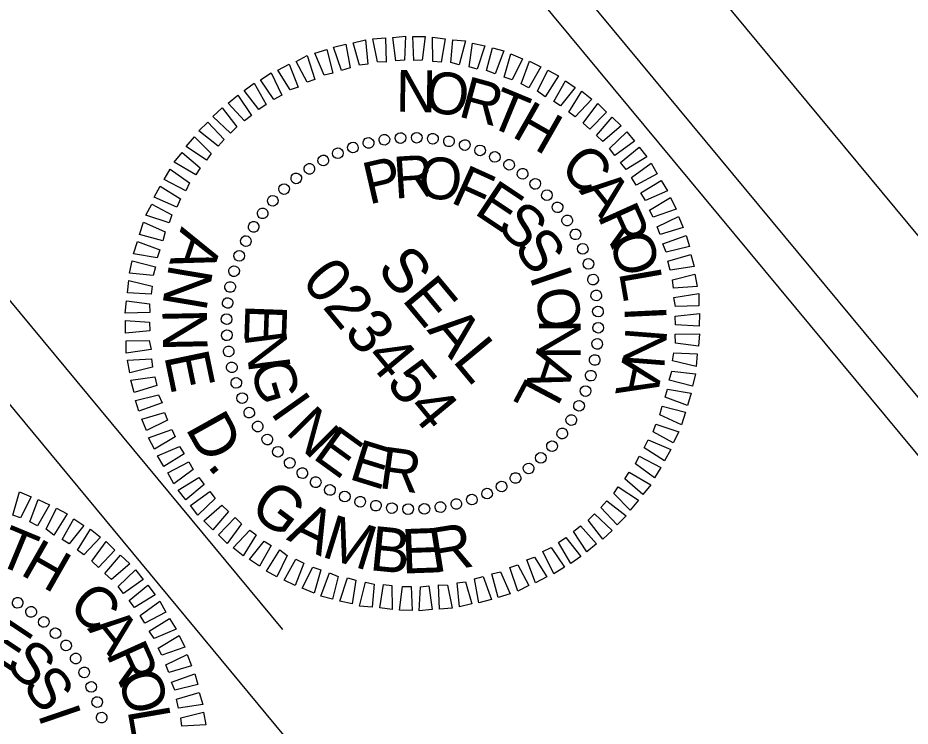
# Model space of a CAD drawing. Extents: x 2054826 to 2060231, y 685508 to 690809.
# Drawn here: x 2058800.7 to 2058981.3, y 687724.9 to 687868.3 of the extents above; entities that cross this region are included whole.
import ezdxf

# ---------------------------------------------------------------- set-up
doc = ezdxf.new("R2010")
doc.units = 0
for name, color, linetype in [('Old_Level_21', 7, 'Continuous'), ('Sheet Professional Seal CELL', 7, 'Continuous'), ('Sheet Title CELL', 7, 'Continuous')]:
    doc.layers.add(name, color=color, linetype=linetype)

msp = doc.modelspace()

# ---------------------------------------------------------------- linework, layer by layer
at = {"layer": 'Old_Level_21'}
msp.add_lwpolyline([(2058588.27, 689338), (2059498.4, 688240.46), (2058988.43, 687817.56), (2058078.29, 688915.11)], close=True, dxfattribs=at)
at = {"layer": 'Sheet Professional Seal CELL'}
for p, q in [((2058874.87, 687843.74), (2058874.87, 687843.74)), ((2058878.15, 687844.02), (2058878.15, 687844.02)), ((2058881.46, 687844.13), (2058881.46, 687844.13)), ((2058884.69, 687843.89), (2058884.69, 687843.89)), ((2058888, 687843.42), (2058888, 687843.42)), ((2058868.49, 687842.15), (2058868.49, 687842.15)), ((2058871.66, 687843.02), (2058871.66, 687843.02)), ((2058891.12, 687842.59), (2058891.12, 687842.59)), ((2058894.26, 687841.5), (2058894.26, 687841.5)), ((2058865.4, 687840.95), (2058865.4, 687840.95)), ((2058897.29, 687840.21), (2058897.29, 687840.21)), ((2058862.54, 687839.46), (2058862.54, 687839.46)), ((2058900.12, 687838.66), (2058900.12, 687838.66)), ((2058859.72, 687837.8), (2058859.72, 687837.8)), ((2058902.83, 687836.81), (2058902.83, 687836.81)), ((2058857.04, 687835.87), (2058857.04, 687835.87)), ((2058905.4, 687834.66), (2058905.4, 687834.66)), ((2058854.55, 687833.7), (2058854.55, 687833.7)), ((2058907.8, 687832.46), (2058907.8, 687832.46)), ((2058852.35, 687831.3), (2058852.35, 687831.3)), ((2058909.96, 687829.97), (2058909.96, 687829.97)), ((2058850.19, 687828.73), (2058850.19, 687828.73)), ((2058911.9, 687827.28), (2058911.9, 687827.28)), ((2058848.34, 687826.03), (2058848.34, 687826.03)), ((2058913.55, 687824.47), (2058913.55, 687824.47)), ((2058846.8, 687823.19), (2058846.8, 687823.19)), ((2058915.04, 687821.61), (2058915.04, 687821.61)), ((2058845.51, 687820.17), (2058845.51, 687820.17)), ((2058916.25, 687818.52), (2058916.25, 687818.52)), ((2058844.41, 687817.02), (2058844.41, 687817.02)), ((2058917.12, 687815.35), (2058917.12, 687815.35)), ((2058843.59, 687813.9), (2058843.59, 687813.9)), ((2058917.83, 687812.14), (2058917.83, 687812.14)), ((2058843.12, 687810.59), (2058843.12, 687810.59)), ((2058842.87, 687807.36), (2058842.87, 687807.36)), ((2058918.11, 687808.86), (2058918.11, 687808.86)), ((2058880.55, 687806.46), (2058880.55, 687806.46)), ((2058918.23, 687805.55), (2058918.23, 687805.55)), ((2058842.99, 687804.05), (2058842.99, 687804.05)), ((2058917.98, 687802.32), (2058917.98, 687802.32)), ((2058843.27, 687800.77), (2058843.27, 687800.77)), ((2058917.51, 687799.01), (2058917.51, 687799.01)), ((2058843.98, 687797.56), (2058843.98, 687797.56)), ((2058916.69, 687795.89), (2058916.69, 687795.89)), ((2058844.86, 687794.39), (2058844.86, 687794.39)), ((2058915.6, 687792.74), (2058915.6, 687792.74)), ((2058846.06, 687791.3), (2058846.06, 687791.3)), ((2058914.3, 687789.72), (2058914.3, 687789.72)), ((2058847.55, 687788.44), (2058847.55, 687788.44)), ((2058849.21, 687785.63), (2058849.21, 687785.63)), ((2058912.76, 687786.88), (2058912.76, 687786.88)), ((2058910.91, 687784.18), (2058910.91, 687784.18)), ((2058851.14, 687782.94), (2058851.14, 687782.94)), ((2058853.3, 687780.45), (2058853.3, 687780.45)), ((2058908.75, 687781.61), (2058908.75, 687781.61)), ((2058855.71, 687778.25), (2058855.71, 687778.25)), ((2058906.56, 687779.21), (2058906.56, 687779.21)), ((2058904.07, 687777.04), (2058904.07, 687777.04)), ((2058858.28, 687776.1), (2058858.28, 687776.1)), ((2058901.38, 687775.11), (2058901.38, 687775.11)), ((2058860.98, 687774.25), (2058860.98, 687774.25)), ((2058898.56, 687773.45), (2058898.56, 687773.45)), ((2058863.82, 687772.7), (2058863.82, 687772.7)), ((2058866.84, 687771.41), (2058866.84, 687771.41)), ((2058895.71, 687771.96), (2058895.71, 687771.96)), ((2058869.99, 687770.32), (2058869.99, 687770.32)), ((2058873.11, 687769.49), (2058873.11, 687769.49)), ((2058889.44, 687769.89), (2058889.44, 687769.89)), ((2058892.61, 687770.76), (2058892.61, 687770.76)), ((2058876.42, 687769.02), (2058876.42, 687769.02)), ((2058879.65, 687768.78), (2058879.65, 687768.78)), ((2058882.96, 687768.89), (2058882.96, 687768.89)), ((2058886.23, 687769.17), (2058886.23, 687769.17)), ((2058803.37, 687748.12), (2058803.37, 687748.12)), ((2058805.94, 687745.96), (2058805.94, 687745.96)), ((2058808.35, 687743.76), (2058808.35, 687743.76)), ((2058810.51, 687741.27), (2058810.51, 687741.27)), ((2058812.44, 687738.59), (2058812.44, 687738.59)), ((2058814.1, 687735.77), (2058814.1, 687735.77)), ((2058815.59, 687732.91), (2058815.59, 687732.91)), ((2058816.79, 687729.82), (2058816.79, 687729.82)), ((2058817.67, 687726.65), (2058817.67, 687726.65))]:
    msp.add_line(p, q, dxfattribs=at)
for points in [[(2058869.83, 687858.75), (2058868.54, 687863.24), (2058871.05, 687863.85), (2058871.5, 687858.97)], [(2058873.46, 687859.42), (2058872.51, 687864.09), (2058875.08, 687864.28), (2058875.26, 687859.36)], [(2058877.2, 687859.61), (2058876.58, 687864.35), (2058879.17, 687864.64), (2058878.92, 687859.76)], [(2058880.83, 687859.69), (2058880.6, 687864.56), (2058883.15, 687864.54), (2058882.54, 687859.75)], [(2058884.7, 687859.49), (2058884.63, 687864.4), (2058887.15, 687864.06), (2058886.39, 687859.33)], [(2058888.3, 687859.26), (2058888.74, 687863.91), (2058891.27, 687863.67), (2058890.02, 687858.83)], [(2058892.01, 687858.44), (2058892.72, 687863.22), (2058895.23, 687862.66), (2058893.67, 687857.96)], [(2058862.72, 687856.75), (2058860.79, 687861.19), (2058863.2, 687861.92), (2058864.46, 687857.12)], [(2058866.21, 687857.7), (2058864.57, 687862.38), (2058867.08, 687863), (2058867.96, 687858.18)], [(2058895.56, 687857.68), (2058896.73, 687862.26), (2058899.08, 687861.66), (2058897.31, 687856.98)], [(2058859.23, 687855.32), (2058857.01, 687859.52), (2058859.25, 687860.7), (2058860.82, 687855.86)], [(2058899.11, 687856.34), (2058900.46, 687861.06), (2058902.86, 687860.03), (2058900.71, 687855.81)], [(2058902.55, 687855), (2058904.26, 687859.53), (2058906.55, 687858.41), (2058904.13, 687854.16)], [(2058855.83, 687853.77), (2058853.33, 687857.73), (2058855.63, 687858.96), (2058857.43, 687854.31)], [(2058905.87, 687853.47), (2058907.98, 687857.74), (2058910.11, 687856.59), (2058907.42, 687852.31)], [(2058852.51, 687851.79), (2058849.79, 687855.77), (2058851.94, 687857.17), (2058854.13, 687852.65)], [(2058849.5, 687849.78), (2058846.5, 687853.63), (2058848.5, 687855.09), (2058850.98, 687850.81)], [(2058909.14, 687851.4), (2058911.51, 687855.6), (2058913.51, 687854.25), (2058910.55, 687850.53)], [(2058846.56, 687847.45), (2058843.28, 687851.05), (2058845.24, 687852.68), (2058847.95, 687848.59)], [(2058912.19, 687849.26), (2058914.82, 687853.48), (2058916.85, 687851.86), (2058913.49, 687848.28)], [(2058915.12, 687847.01), (2058918.05, 687851), (2058919.81, 687849.24), (2058916.45, 687845.77)], [(2058843.72, 687844.99), (2058840.15, 687848.36), (2058842.02, 687850.11), (2058845.01, 687846.26)], [(2058841.24, 687842.35), (2058837.32, 687845.43), (2058839.14, 687847.23), (2058842.43, 687843.73)], [(2058917.77, 687844.53), (2058920.94, 687848.23), (2058922.8, 687846.45), (2058919.09, 687843.28)], [(2058920.45, 687841.88), (2058923.96, 687845.28), (2058925.49, 687843.33), (2058921.54, 687840.45)], [(2058838.9, 687839.53), (2058834.79, 687842.26), (2058836.46, 687844.23), (2058839.82, 687840.88)], [(2058922.69, 687839.06), (2058926.44, 687842.17), (2058927.97, 687840.22), (2058923.78, 687837.63)], [(2058836.7, 687836.54), (2058832.31, 687839.13), (2058833.93, 687841.06), (2058837.58, 687837.95)], [(2058924.91, 687836.03), (2058928.86, 687838.91), (2058930.09, 687836.72), (2058925.83, 687834.45)], [(2058834.7, 687833.32), (2058830.28, 687835.6), (2058831.54, 687837.72), (2058835.43, 687834.9)], [(2058832.85, 687830.03), (2058828.29, 687832), (2058829.51, 687834.28), (2058833.64, 687831.66)], [(2058926.75, 687832.88), (2058930.87, 687835.42), (2058932.16, 687833.28), (2058927.72, 687831.35)], [(2058831.32, 687826.82), (2058826.62, 687828.37), (2058827.79, 687830.61), (2058831.84, 687828.42)], [(2058928.55, 687829.41), (2058932.79, 687831.94), (2058933.95, 687829.59), (2058929.27, 687827.95)], [(2058930.1, 687826.01), (2058934.4, 687828.11), (2058935.31, 687825.85), (2058930.7, 687824.46)], [(2058830.02, 687823.21), (2058825.29, 687824.45), (2058826.12, 687826.98), (2058830.51, 687824.98)], [(2058931.22, 687822.55), (2058935.96, 687824.24), (2058936.6, 687822.05), (2058931.91, 687820.89)], [(2058828.9, 687819.75), (2058824.13, 687820.56), (2058824.9, 687823.05), (2058829.42, 687821.35)], [(2058932.27, 687819.04), (2058936.88, 687820.43), (2058937.55, 687817.97), (2058932.69, 687817.25)], [(2058828.09, 687816.15), (2058823.29, 687816.65), (2058823.84, 687819.15), (2058828.57, 687817.91)], [(2058933.15, 687815.29), (2058937.73, 687816.46), (2058938.19, 687813.91), (2058933.37, 687813.62)], [(2058827.68, 687812.4), (2058822.91, 687812.63), (2058823.15, 687815.17), (2058827.89, 687814.03)], [(2058827.39, 687808.65), (2058822.42, 687808.53), (2058822.66, 687811.06), (2058827.34, 687810.46)], [(2058933.46, 687811.74), (2058938.48, 687812.5), (2058938.51, 687809.99), (2058933.82, 687809.9)], [(2058933.69, 687807.94), (2058938.63, 687808.44), (2058938.61, 687805.88), (2058933.79, 687806.17)], [(2058827.42, 687804.97), (2058822.47, 687804.47), (2058822.5, 687807.03), (2058827.32, 687806.74)], [(2058933.72, 687804.26), (2058938.68, 687804.38), (2058938.45, 687801.85), (2058933.76, 687802.45)], [(2058827.65, 687801.17), (2058822.62, 687800.41), (2058822.59, 687802.92), (2058827.29, 687803.01)], [(2058933.42, 687800.51), (2058938.19, 687800.28), (2058937.96, 687797.74), (2058933.21, 687798.88)], [(2058827.96, 687797.62), (2058823.37, 687796.45), (2058822.92, 687799), (2058827.74, 687799.29)], [(2058933.02, 687796.76), (2058937.82, 687796.26), (2058937.26, 687793.76), (2058932.53, 687795)], [(2058828.83, 687793.87), (2058824.23, 687792.48), (2058823.55, 687794.94), (2058828.41, 687795.66)], [(2058932.2, 687793.17), (2058936.97, 687792.35), (2058936.21, 687789.86), (2058931.68, 687791.56)], [(2058829.89, 687790.36), (2058825.15, 687788.67), (2058824.5, 687790.86), (2058829.19, 687792.02)], [(2058931.08, 687789.7), (2058935.81, 687788.46), (2058934.99, 687785.93), (2058930.6, 687787.94)], [(2058831, 687786.9), (2058826.71, 687784.8), (2058825.8, 687787.06), (2058830.4, 687788.45)], [(2058929.78, 687786.09), (2058934.49, 687784.54), (2058933.32, 687782.3), (2058929.26, 687784.49)], [(2058832.55, 687783.51), (2058828.32, 687780.97), (2058827.15, 687783.32), (2058831.83, 687784.96)], [(2058928.26, 687782.88), (2058932.82, 687780.91), (2058931.59, 687778.63), (2058927.47, 687781.25)], [(2058834.36, 687780.03), (2058830.23, 687777.49), (2058828.94, 687779.63), (2058833.38, 687781.56)], [(2058836.19, 687776.88), (2058832.25, 687774), (2058831.02, 687776.19), (2058835.27, 687778.46)], [(2058926.41, 687779.59), (2058930.83, 687777.31), (2058929.57, 687775.19), (2058925.67, 687778.01)], [(2058838.41, 687773.85), (2058834.66, 687770.74), (2058833.14, 687772.69), (2058837.32, 687775.28)], [(2058924.4, 687776.37), (2058928.79, 687773.78), (2058927.18, 687771.85), (2058923.53, 687774.96)], [(2058922.21, 687773.38), (2058926.32, 687770.65), (2058924.64, 687768.68), (2058921.28, 687772.03)], [(2058799.66, 687767.64), (2058801, 687772.36), (2058803.41, 687771.34), (2058801.26, 687767.11)], [(2058840.65, 687771.03), (2058837.14, 687767.63), (2058835.62, 687769.58), (2058839.56, 687772.46)], [(2058803.1, 687766.3), (2058804.8, 687770.83), (2058807.09, 687769.71), (2058804.67, 687765.46)], [(2058843.34, 687768.38), (2058840.17, 687764.68), (2058838.31, 687766.46), (2058842.01, 687769.63)], [(2058919.87, 687770.56), (2058923.79, 687767.48), (2058921.97, 687765.68), (2058918.67, 687769.18)], [(2058806.42, 687764.77), (2058808.52, 687769.05), (2058810.65, 687767.89), (2058807.96, 687763.61)], [(2058917.38, 687767.92), (2058920.96, 687764.55), (2058919.09, 687762.8), (2058916.09, 687766.65)], [(2058809.69, 687762.71), (2058812.05, 687766.91), (2058814.05, 687765.55), (2058811.1, 687761.83)], [(2058845.98, 687765.9), (2058843.05, 687761.91), (2058841.3, 687763.67), (2058844.66, 687767.14)], [(2058812.74, 687760.56), (2058815.37, 687764.79), (2058817.4, 687763.16), (2058814.03, 687759.58)], [(2058848.91, 687763.66), (2058846.28, 687759.43), (2058844.25, 687761.05), (2058847.62, 687764.63)], [(2058914.54, 687765.47), (2058917.83, 687761.86), (2058915.87, 687760.23), (2058913.16, 687764.32)], [(2058815.67, 687758.31), (2058818.6, 687762.3), (2058820.35, 687760.54), (2058816.99, 687757.07)], [(2058851.96, 687761.51), (2058849.6, 687757.31), (2058847.6, 687758.66), (2058850.55, 687762.38)], [(2058911.61, 687763.13), (2058914.61, 687759.28), (2058912.6, 687757.82), (2058910.13, 687762.1)], [(2058855.23, 687759.44), (2058853.13, 687755.17), (2058851, 687756.32), (2058853.69, 687760.6)], [(2058908.6, 687761.12), (2058911.32, 687757.14), (2058909.16, 687755.74), (2058906.97, 687760.26)], [(2058818.31, 687755.83), (2058821.48, 687759.53), (2058823.34, 687757.76), (2058819.64, 687754.59)], [(2058858.55, 687757.91), (2058856.85, 687753.38), (2058854.56, 687754.5), (2058856.98, 687758.75)], [(2058905.27, 687759.14), (2058907.78, 687755.18), (2058905.48, 687753.95), (2058903.68, 687758.6)], [(2058821, 687753.18), (2058824.51, 687756.58), (2058826.03, 687754.63), (2058822.09, 687751.75)], [(2058861.99, 687756.58), (2058860.65, 687751.85), (2058858.24, 687752.88), (2058860.39, 687757.1)], [(2058901.88, 687757.59), (2058904.1, 687753.39), (2058901.85, 687752.22), (2058900.28, 687757.05)], [(2058865.54, 687755.23), (2058864.37, 687750.65), (2058862.03, 687751.25), (2058863.8, 687755.93)], [(2058869.1, 687754.47), (2058868.38, 687749.69), (2058865.88, 687750.25), (2058867.44, 687754.95)], [(2058894.89, 687755.21), (2058896.53, 687750.53), (2058894.02, 687749.91), (2058893.14, 687754.73)], [(2058898.39, 687756.16), (2058900.32, 687751.72), (2058897.91, 687750.99), (2058896.65, 687755.79)], [(2058823.24, 687750.36), (2058826.99, 687753.47), (2058828.51, 687751.52), (2058824.33, 687748.93)], [(2058872.8, 687753.65), (2058872.37, 687749), (2058869.83, 687749.24), (2058871.08, 687754.08)], [(2058876.4, 687753.42), (2058876.48, 687748.51), (2058873.95, 687748.85), (2058874.71, 687753.58)], [(2058880.27, 687753.22), (2058880.51, 687748.35), (2058877.95, 687748.37), (2058878.56, 687753.16)], [(2058883.9, 687753.31), (2058884.52, 687748.56), (2058881.94, 687748.27), (2058882.18, 687753.15)], [(2058887.65, 687753.49), (2058888.59, 687748.82), (2058886.02, 687748.63), (2058885.84, 687753.55)], [(2058891.28, 687754.16), (2058892.56, 687749.67), (2058890.05, 687749.06), (2058889.61, 687753.94)], [(2058825.46, 687747.33), (2058829.4, 687750.21), (2058830.63, 687748.02), (2058826.38, 687745.76)], [(2058827.29, 687744.18), (2058831.42, 687746.72), (2058832.71, 687744.58), (2058828.27, 687742.65)], [(2058829.1, 687740.71), (2058833.33, 687743.24), (2058834.5, 687740.9), (2058829.82, 687739.26)], [(2058830.65, 687737.31), (2058834.94, 687739.42), (2058835.85, 687737.15), (2058831.25, 687735.77)], [(2058831.76, 687733.85), (2058836.5, 687735.54), (2058837.15, 687733.35), (2058832.46, 687732.19)], [(2058832.82, 687730.35), (2058837.42, 687731.73), (2058838.1, 687729.27), (2058833.24, 687728.55)], [(2058833.69, 687726.59), (2058838.28, 687727.76), (2058838.73, 687725.21), (2058833.91, 687724.92)]]:
    msp.add_lwpolyline(points, close=True, dxfattribs=at)
for centre, major_axis in [((2058878.15, 687844), (-0.07, 1.08)), ((2058881.43, 687844.07), (0.03, 1.08)), ((2058868.51, 687842.1), (-0.35, 1.02)), ((2058871.66, 687843.01), (-0.26, 1.05)), ((2058874.88, 687843.65), (-0.16, 1.07)), ((2058884.7, 687843.85), (0.12, 1.07)), ((2058887.94, 687843.34), (0.21, 1.06)), ((2058891.13, 687842.56), (0.3, 1.04)), ((2058865.45, 687840.91), (-0.434, 0.989)), ((2058894.24, 687841.5), (0.39, 1.01)), ((2058862.51, 687839.46), (-0.518, 0.948)), ((2058897.24, 687840.17), (0.479, 0.968)), ((2058900.12, 687838.59), (0.562, 0.922)), ((2058859.7, 687837.77), (-0.599, 0.899)), ((2058902.84, 687836.76), (0.64, 0.87)), ((2058857.05, 687835.83), (-0.675, 0.843)), ((2058854.58, 687833.67), (-0.746, 0.781)), ((2058905.4, 687834.7), (0.713, 0.811)), ((2058852.3, 687831.3), (-0.811, 0.713)), ((2058907.77, 687832.43), (0.781, 0.746)), ((2058909.93, 687829.96), (0.843, 0.675)), ((2058850.25, 687828.74), (-0.87, 0.64)), ((2058848.42, 687826.02), (-0.922, 0.562)), ((2058911.86, 687827.31), (0.899, 0.599)), ((2058913.56, 687824.5), (0.948, 0.518)), ((2058846.84, 687823.14), (-0.968, 0.479)), ((2058915.01, 687821.56), (0.989, 0.434)), ((2058845.51, 687820.14), (-1.01, 0.39)), ((2058844.45, 687817.03), (-1.04, 0.3)), ((2058916.19, 687818.5), (1.02, 0.35)), ((2058917.11, 687815.34), (1.05, 0.26)), ((2058843.67, 687813.85), (-1.06, 0.21)), ((2058917.74, 687812.12), (1.07, 0.16)), ((2058843.16, 687810.6), (-1.07, 0.12)), ((2058918.1, 687808.86), (1.08, 0.07)), ((2058842.94, 687807.33), (-1.08, 0.03)), ((2058918.16, 687805.58), (1.08, -0.03)), ((2058843.01, 687804.05), (-1.08, -0.07)), ((2058843.36, 687800.79), (-1.07, -0.16)), ((2058917.94, 687802.31), (1.07, -0.12)), ((2058917.44, 687799.06), (1.06, -0.21)), ((2058844, 687797.57), (-1.05, -0.26)), ((2058916.65, 687795.88), (1.04, -0.3)), ((2058844.91, 687794.41), (-1.02, -0.35)), ((2058915.59, 687792.77), (1.01, -0.39)), ((2058846.1, 687791.35), (-0.989, -0.434)), ((2058914.27, 687789.77), (0.968, -0.479)), ((2058847.54, 687788.41), (-0.948, -0.518)), ((2058912.69, 687786.89), (0.922, -0.562)), ((2058849.24, 687785.6), (-0.899, -0.599)), ((2058851.18, 687782.95), (-0.843, -0.675)), ((2058910.86, 687784.17), (0.87, -0.64)), ((2058908.8, 687781.61), (0.811, -0.713)), ((2058853.34, 687780.48), (-0.781, -0.746)), ((2058906.53, 687779.24), (0.746, -0.781)), ((2058855.71, 687778.21), (-0.713, -0.811)), ((2058904.06, 687777.08), (0.675, -0.843)), ((2058858.26, 687776.15), (-0.64, -0.87)), ((2058860.99, 687774.32), (-0.562, -0.922)), ((2058898.6, 687773.45), (0.518, -0.948)), ((2058901.41, 687775.15), (0.599, -0.899)), ((2058863.86, 687772.74), (-0.479, -0.968)), ((2058895.65, 687772), (0.434, -0.989)), ((2058866.87, 687771.41), (-0.39, -1.01)), ((2058869.97, 687770.35), (-0.3, -1.04)), ((2058889.44, 687769.9), (0.26, -1.05)), ((2058892.59, 687770.81), (0.35, -1.02)), ((2058873.16, 687769.57), (-0.21, -1.06)), ((2058876.4, 687769.06), (-0.12, -1.07)), ((2058879.68, 687768.85), (-0.03, -1.08)), ((2058882.96, 687768.91), (0.07, -1.08)), ((2058886.22, 687769.26), (0.16, -1.07)), ((2058800.66, 687749.89), (0.562, 0.922)), ((2058803.39, 687748.06), (0.64, 0.87)), ((2058805.94, 687746.01), (0.713, 0.811)), ((2058808.31, 687743.73), (0.781, 0.746)), ((2058810.47, 687741.26), (0.843, 0.675)), ((2058812.41, 687738.61), (0.899, 0.599)), ((2058814.11, 687735.8), (0.948, 0.518)), ((2058815.55, 687732.86), (0.989, 0.434)), ((2058816.74, 687729.8), (1.02, 0.35)), ((2058817.65, 687726.65), (1.05, 0.26))]:
    msp.add_ellipse(centre, major_axis=major_axis, ratio=0.999708, dxfattribs=at)
at = {"layer": 'Sheet Title CELL'}
for p, q in [((2057819.13, 689194.85), (2059178.76, 687555.25)), ((2058813.93, 687983.46), (2059005.21, 687752.79)), ((2058714.94, 687912.46), (2058854.25, 687744.46)), ((2058699.6, 687909.89), (2058910.89, 687655.09))]:
    msp.add_line(p, q, dxfattribs=at)

# ---------------------------------------------------------------- texts
at = {"layer": 'Sheet Professional Seal CELL'}
for s, height, rotation, p in [('N', 8.46, 359.0907, (2058877.15, 687849.33)), ('O', 8.46, 351.8889, (2058882.7, 687849.45)), ('R', 8.46, 344.6877, (2058889.58, 687848.44)), ('T', 8.46, 337.487, (2058895.38, 687846.62)), ('H', 8.46, 330.2867, (2058900.4, 687844.44)), ('C', 8.46, 315.8871, (2058909.98, 687837.58)), ('P', 8.46, 13.0661, (2058871.72, 687830.5)), ('R', 8.46, 3.7069, (2058876.95, 687831.72)), ('O', 8.46, 354.3484, (2058881.45, 687832.04)), ('F', 8.46, 335.6342, (2058888.02, 687831.06)), ('A', 8.46, 308.6875, (2058914.11, 687833.31)), ('E', 8.46, 326.2783, (2058892.81, 687828.8)), ('S', 8.46, 316.9228, (2058897.33, 687825.82)), ('R', 8.46, 294.2883, (2058917.9, 687828.27)), ('A', 9, 251.5406, (2058833.84, 687826.16)), ('S', 8.46, 307.5676, (2058900.83, 687821.71)), ('O', 8.46, 287.0884, (2058920.24, 687823.68)), ('SEAL', 8.997, 309.6672, (2058873.11, 687817.43)), ('023454', 8.997, 309.6672, (2058857.91, 687814.94)), ('N', 9, 260.3809, (2058831.36, 687818.75)), ('I', 8.46, 288.8568, (2058904.14, 687816.08)), ('L', 8.46, 279.8881, (2058922.32, 687816.83)), ('O', 8.46, 279.5007, (2058905.25, 687813.1)), ('E', 8.46, 267.9441, (2058846.78, 687810.41)), ('I', 8.46, 272.6873, (2058923.43, 687809.86)), ('N', 9, 271.1068, (2058829.94, 687809.38)), ('N', 8.46, 270.1438, (2058906.15, 687807.32)), ('N', 8.46, 277.3012, (2058846.53, 687804.36)), ('N', 8.46, 265.4861, (2058923.7, 687805.89)), ('E', 9, 281.8326, (2058830.28, 687799.91)), ('A', 8.46, 251.4275, (2058905.87, 687801.54)), ('G', 8.46, 286.6574, (2058847.57, 687797.82)), ('A', 8.46, 258.2844, (2058923.11, 687799.66)), ('L', 8.46, 242.0681, (2058903.76, 687795.98)), ('I', 8.46, 305.3684, (2058851.65, 687788.43)), ('N', 8.46, 314.7236, (2058854.69, 687784.42)), ('D', 9, 299.1423, (2058834.5, 687785.24)), ('E', 8.46, 324.079, (2058860.12, 687779.28)), ('E', 8.46, 342.7913, (2058867.45, 687775.03)), ('R', 8.46, 352.1486, (2058873.56, 687773.18)), ('.', 9, 309.0181, (2058838.82, 687777.66)), ('G', 9, 323.2522, (2058847.18, 687768.28)), ('A', 9, 333.9781, (2058854.87, 687762.74)), ('M', 9, 342.8184, (2058861.89, 687759.31)), ('T', 8.46, 337.487, (2058795.93, 687757.92)), ('R', 9, 9.1538, (2058884.74, 687755.93)), ('B', 9, 354.3479, (2058871.69, 687756.53)), ('E', 9, 2.0445, (2058878.46, 687755.8)), ('H', 8.46, 330.2867, (2058800.94, 687755.75)), ('C', 8.46, 315.8871, (2058810.53, 687748.89)), ('E', 8.46, 326.2783, (2058793.36, 687740.1)), ('A', 8.46, 308.6875, (2058814.66, 687744.61)), ('R', 8.46, 294.2883, (2058818.45, 687739.57)), ('S', 8.46, 316.9228, (2058797.87, 687737.12)), ('S', 8.46, 307.5676, (2058801.38, 687733.02)), ('O', 8.46, 287.0884, (2058820.79, 687734.98)), ('I', 8.46, 288.8568, (2058804.69, 687727.38)), ('L', 8.46, 279.8881, (2058822.87, 687728.13))]:
    msp.add_text(s, height=height, rotation=rotation, dxfattribs=at).set_placement(p)

doc.saveas('drawing.dxf')
